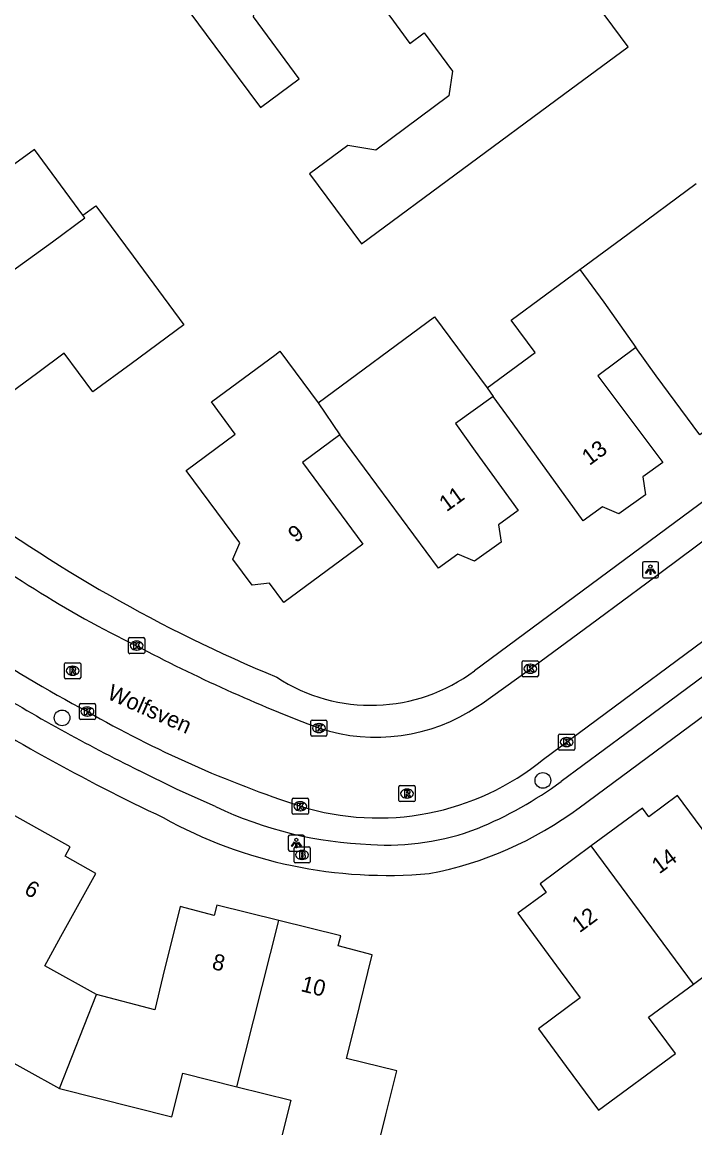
# Model space of a CAD drawing. Extents: x 163427 to 164190, y 380331 to 381641.
# Drawn here: x 163788.9 to 163830.8, y 381101.7 to 381170.4 of the extents above; entities that cross this region are included whole.
import ezdxf

# ---------------------------------------------------------------- set-up
doc = ezdxf.new("R2010")
doc.units = 0
for name, color, linetype in [('IMGEO_Boom', 7, 'Continuous'), ('IMGEO_Brandkraan', 7, 'Continuous'), ('IMGEO_Kolk', 7, 'Continuous'), ('IMGEO_Lichtpunt', 7, 'Continuous'), ('IMGEO_Openbare_ruimte_label', 7, 'Continuous'), ('IMGEO_Pand', 7, 'Continuous'), ('IMGEO_Pand_nummerreeks', 7, 'Continuous'), ('IMGEO_Rijbaan_lokaal_open', 7, 'Continuous'), ('IMGEO_Rioolput', 7, 'Continuous'), ('IMGEO_Voetpad_open', 7, 'Continuous')]:
    doc.layers.add(name, color=color, linetype=linetype)

msp = doc.modelspace()

# ---------------------------------------------------------------- linework, layer by layer
at = {"layer": 'IMGEO_Boom'}
for centre in [(163791.427, 381127.162), (163821.325, 381123.271)]:
    msp.add_circle(centre, 0.489, dxfattribs=at)
at = {"layer": 'IMGEO_Brandkraan'}
for p, q in [((163805.85, 381118.213), (163805.85, 381119.065)), ((163805.925, 381119.139), (163806.777, 381119.139)), ((163806.338, 381118.919), (163806.363, 381118.919)), ((163806.851, 381119.065), (163806.851, 381118.213)), ((163806.361, 381118.359), (163806.336, 381118.359)), ((163806.777, 381118.139), (163805.925, 381118.139))]:
    msp.add_line(p, q, dxfattribs=at)
for points in [[(163805.85, 381118.213), (163805.85, 381119.065)], [(163805.925, 381119.139), (163806.777, 381119.139)], [(163806.851, 381119.065), (163806.851, 381118.213)], [(163806.198, 381118.839), (163806.198, 381118.439), (163806.411, 381118.439)], [(163806.429, 381118.839), (163806.198, 381118.839)], [(163806.377, 381118.758), (163806.323, 381118.758), (163806.323, 381118.682)], [(163806.323, 381118.682), (163806.376, 381118.682)], [(163806.385, 381118.606), (163806.323, 381118.606), (163806.323, 381118.525)], [(163806.323, 381118.525), (163806.385, 381118.525)], [(163806.777, 381118.139), (163805.925, 381118.139)]]:
    msp.add_lwpolyline(points, dxfattribs=at)
for centre, radius, start, end in [((163805.927, 381119.063), 0.0765, 91.55205, 178.44795), ((163805.927, 381119.063), 0.0765, 91.55205, 178.44795), ((163806.775, 381119.063), 0.0765, 1.55205, 88.44795), ((163806.775, 381119.063), 0.0765, 1.55205, 88.44795), ((163805.927, 381118.215), 0.0765, 181.55205, 268.44795), ((163805.927, 381118.215), 0.0765, 181.55205, 268.44795), ((163806.378, 381118.72), 0.0379, 267.82845, 90.93552), ((163806.386, 381118.565), 0.0404, 269.87594, 90.50774), ((163806.417, 381118.69), 0.251, 268.66757, 293.53466), ((163806.433, 381118.694), 0.145, 59.4692, 91.53667), ((163806.458, 381118.741), 0.0922, 285.51372, 58.15012), ((163806.463, 381118.549), 0.105, 301.31148, 78.98903), ((163806.775, 381118.215), 0.0765, 271.55205, 358.44795), ((163806.775, 381118.215), 0.0765, 271.55205, 358.44795)]:
    msp.add_arc(centre, radius, start, end, dxfattribs=at)
for centre, major_axis, ratio, start_param, end_param in [((163806.337, 381118.639), (-0.387, 0.002), 0.722429, 4.712389, 7.853982), ((163806.362, 381118.639), (-0.39, 0.002), 0.717154, 1.570796, 4.712389)]:
    msp.add_ellipse(centre, major_axis=major_axis, ratio=ratio, start_param=start_param, end_param=end_param, dxfattribs=at)
at = {"layer": 'IMGEO_Kolk'}
for p, q in [((163795.563, 381131.229), (163795.563, 381132.081)), ((163795.638, 381132.155), (163796.49, 381132.155)), ((163796.051, 381131.935), (163796.076, 381131.935)), ((163796.564, 381132.081), (163796.564, 381131.229)), ((163796.074, 381131.375), (163796.049, 381131.375)), ((163796.49, 381131.155), (163795.638, 381131.155)), ((163820.041, 381129.792), (163820.041, 381130.644)), ((163820.116, 381130.718), (163820.968, 381130.718)), ((163821.042, 381130.644), (163821.042, 381129.792)), ((163820.552, 381129.938), (163820.527, 381129.938)), ((163820.529, 381130.498), (163820.554, 381130.498)), ((163820.968, 381129.718), (163820.116, 381129.718)), ((163792.504, 381127.129), (163792.504, 381127.981)), ((163792.579, 381128.055), (163793.431, 381128.055)), ((163792.992, 381127.835), (163793.017, 381127.835)), ((163793.505, 381127.981), (163793.505, 381127.129)), ((163793.015, 381127.275), (163792.99, 381127.275)), ((163793.431, 381127.055), (163792.579, 381127.055)), ((163806.897, 381126.103), (163806.897, 381126.955)), ((163806.972, 381127.029), (163807.824, 381127.029)), ((163807.385, 381126.809), (163807.41, 381126.809)), ((163807.898, 381126.955), (163807.898, 381126.103)), ((163807.824, 381126.029), (163806.972, 381126.029)), ((163807.408, 381126.249), (163807.383, 381126.249)), ((163822.303, 381125.232), (163822.303, 381126.084)), ((163822.378, 381126.158), (163823.23, 381126.158)), ((163822.791, 381125.938), (163822.816, 381125.938)), ((163823.304, 381126.084), (163823.304, 381125.232)), ((163823.23, 381125.158), (163822.378, 381125.158)), ((163822.814, 381125.378), (163822.789, 381125.378)), ((163805.741, 381121.241), (163805.741, 381122.093)), ((163805.816, 381122.167), (163806.668, 381122.167)), ((163806.229, 381121.947), (163806.254, 381121.947)), ((163806.742, 381122.093), (163806.742, 381121.241)), ((163806.668, 381121.167), (163805.816, 381121.167)), ((163806.252, 381121.387), (163806.227, 381121.387))]:
    msp.add_line(p, q, dxfattribs=at)
for points in [[(163795.563, 381131.229), (163795.563, 381132.081)], [(163795.638, 381132.155), (163796.49, 381132.155)], [(163796.564, 381132.081), (163796.564, 381131.229)], [(163795.884, 381131.855), (163796.007, 381131.855), (163796.007, 381131.704), (163796.137, 381131.855), (163796.301, 381131.855), (163796.155, 381131.704), (163796.308, 381131.455), (163796.156, 381131.455), (163796.071, 381131.619), (163796.007, 381131.552), (163796.007, 381131.455), (163795.884, 381131.455), (163795.884, 381131.855)], [(163796.49, 381131.155), (163795.638, 381131.155)], [(163820.041, 381129.792), (163820.041, 381130.644)], [(163820.116, 381130.718), (163820.968, 381130.718)], [(163821.042, 381130.644), (163821.042, 381129.792)], [(163820.362, 381130.418), (163820.485, 381130.418), (163820.485, 381130.267), (163820.615, 381130.418), (163820.779, 381130.418), (163820.633, 381130.267), (163820.786, 381130.018), (163820.634, 381130.018), (163820.549, 381130.182), (163820.485, 381130.115), (163820.485, 381130.018), (163820.362, 381130.018), (163820.362, 381130.418)], [(163820.968, 381129.718), (163820.116, 381129.718)], [(163792.504, 381127.129), (163792.504, 381127.981)], [(163792.579, 381128.055), (163793.431, 381128.055)], [(163793.505, 381127.981), (163793.505, 381127.129)], [(163792.825, 381127.755), (163792.948, 381127.755), (163792.948, 381127.604), (163793.078, 381127.755), (163793.242, 381127.755), (163793.096, 381127.604), (163793.249, 381127.355), (163793.097, 381127.355), (163793.012, 381127.519), (163792.948, 381127.452), (163792.948, 381127.355), (163792.825, 381127.355), (163792.825, 381127.755)], [(163793.431, 381127.055), (163792.579, 381127.055)], [(163806.897, 381126.103), (163806.897, 381126.955)], [(163806.972, 381127.029), (163807.824, 381127.029)], [(163807.218, 381126.729), (163807.341, 381126.729), (163807.341, 381126.578), (163807.471, 381126.729), (163807.635, 381126.729), (163807.489, 381126.578), (163807.642, 381126.329), (163807.49, 381126.329), (163807.405, 381126.493), (163807.341, 381126.426), (163807.341, 381126.329), (163807.218, 381126.329), (163807.218, 381126.729)], [(163807.898, 381126.955), (163807.898, 381126.103)], [(163807.824, 381126.029), (163806.972, 381126.029)], [(163822.303, 381125.232), (163822.303, 381126.084)], [(163822.378, 381126.158), (163823.23, 381126.158)], [(163822.624, 381125.858), (163822.747, 381125.858), (163822.747, 381125.707), (163822.877, 381125.858), (163823.041, 381125.858), (163822.895, 381125.707), (163823.048, 381125.458), (163822.896, 381125.458), (163822.811, 381125.622), (163822.747, 381125.555), (163822.747, 381125.458), (163822.624, 381125.458), (163822.624, 381125.858)], [(163823.304, 381126.084), (163823.304, 381125.232)], [(163823.23, 381125.158), (163822.378, 381125.158)], [(163805.741, 381121.241), (163805.741, 381122.093)], [(163805.816, 381122.167), (163806.668, 381122.167)], [(163806.062, 381121.867), (163806.185, 381121.867), (163806.185, 381121.716), (163806.315, 381121.867), (163806.479, 381121.867), (163806.333, 381121.716), (163806.486, 381121.467), (163806.334, 381121.467), (163806.249, 381121.631), (163806.185, 381121.564), (163806.185, 381121.467), (163806.062, 381121.467), (163806.062, 381121.867)], [(163806.742, 381122.093), (163806.742, 381121.241)], [(163806.668, 381121.167), (163805.816, 381121.167)]]:
    msp.add_lwpolyline(points, dxfattribs=at)
for centre, start, end in [((163795.64, 381132.079), 91.55205, 178.44795), ((163795.64, 381132.079), 91.55205, 178.44795), ((163796.488, 381132.079), 1.55205, 88.44795), ((163796.488, 381132.079), 1.55205, 88.44795), ((163795.64, 381131.231), 181.55205, 268.44795), ((163795.64, 381131.231), 181.55205, 268.44795), ((163796.488, 381131.231), 271.55205, 358.44795), ((163796.488, 381131.231), 271.55205, 358.44795), ((163820.118, 381130.642), 91.55205, 178.44795), ((163820.118, 381130.642), 91.55205, 178.44795), ((163820.966, 381130.642), 1.55205, 88.44795), ((163820.966, 381130.642), 1.55205, 88.44795), ((163820.118, 381129.794), 181.55205, 268.44795), ((163820.118, 381129.794), 181.55205, 268.44795), ((163820.966, 381129.794), 271.55205, 358.44795), ((163820.966, 381129.794), 271.55205, 358.44795), ((163792.581, 381127.979), 91.55205, 178.44795), ((163792.581, 381127.979), 91.55205, 178.44795), ((163793.429, 381127.979), 1.55205, 88.44795), ((163793.429, 381127.979), 1.55205, 88.44795), ((163792.581, 381127.131), 181.55205, 268.44795), ((163792.581, 381127.131), 181.55205, 268.44795), ((163793.429, 381127.131), 271.55205, 358.44795), ((163793.429, 381127.131), 271.55205, 358.44795), ((163806.974, 381126.953), 91.55205, 178.44795), ((163806.974, 381126.953), 91.55205, 178.44795), ((163807.822, 381126.953), 1.55205, 88.44795), ((163807.822, 381126.953), 1.55205, 88.44795), ((163806.974, 381126.105), 181.55205, 268.44795), ((163806.974, 381126.105), 181.55205, 268.44795), ((163807.822, 381126.105), 271.55205, 358.44795), ((163807.822, 381126.105), 271.55205, 358.44795), ((163822.38, 381126.082), 91.55205, 178.44795), ((163822.38, 381126.082), 91.55205, 178.44795), ((163823.228, 381126.082), 1.55205, 88.44795), ((163823.228, 381126.082), 1.55205, 88.44795), ((163822.38, 381125.234), 181.55205, 268.44795), ((163822.38, 381125.234), 181.55205, 268.44795), ((163823.228, 381125.234), 271.55205, 358.44795), ((163823.228, 381125.234), 271.55205, 358.44795), ((163805.818, 381122.091), 91.55205, 178.44795), ((163805.818, 381122.091), 91.55205, 178.44795), ((163806.666, 381122.091), 1.55205, 88.44795), ((163806.666, 381122.091), 1.55205, 88.44795), ((163805.818, 381121.243), 181.55205, 268.44795), ((163805.818, 381121.243), 181.55205, 268.44795), ((163806.666, 381121.243), 271.55205, 358.44795), ((163806.666, 381121.243), 271.55205, 358.44795)]:
    msp.add_arc(centre, 0.0765, start, end, dxfattribs=at)
for centre, major_axis, ratio, start_param, end_param in [((163796.05, 381131.655), (-0.387, 0.002), 0.722429, 4.712389, 7.853982), ((163796.075, 381131.655), (-0.39, 0.002), 0.717154, 1.570796, 4.712389), ((163820.528, 381130.218), (-0.387, 0.002), 0.722429, 4.712389, 7.853982), ((163820.553, 381130.218), (-0.39, 0.002), 0.717154, 1.570796, 4.712389), ((163792.991, 381127.555), (-0.387, 0.002), 0.722429, 4.712389, 7.853982), ((163793.016, 381127.555), (-0.39, 0.002), 0.717154, 1.570796, 4.712389), ((163807.384, 381126.529), (-0.387, 0.002), 0.722429, 4.712389, 7.853982), ((163807.409, 381126.529), (-0.39, 0.002), 0.717154, 1.570796, 4.712389), ((163822.79, 381125.658), (-0.387, 0.002), 0.722429, 4.712389, 7.853982), ((163822.815, 381125.658), (-0.39, 0.002), 0.717154, 1.570796, 4.712389), ((163806.228, 381121.667), (-0.387, 0.002), 0.722429, 4.712389, 7.853982), ((163806.253, 381121.667), (-0.39, 0.002), 0.717154, 1.570796, 4.712389)]:
    msp.add_ellipse(centre, major_axis=major_axis, ratio=ratio, start_param=start_param, end_param=end_param, dxfattribs=at)
at = {"layer": 'IMGEO_Lichtpunt'}
for p, q in [((163827.514, 381136.775), (163827.514, 381135.968)), ((163827.514, 381136.775), (163827.514, 381135.968)), ((163828.416, 381136.87), (163827.608, 381136.87)), ((163828.416, 381136.87), (163827.608, 381136.87)), ((163828.51, 381135.968), (163828.51, 381136.775)), ((163828.51, 381135.968), (163828.51, 381136.775)), ((163827.608, 381135.874), (163828.416, 381135.874)), ((163827.608, 381135.874), (163828.416, 381135.874)), ((163805.496, 381119.779), (163805.496, 381118.972)), ((163805.496, 381119.779), (163805.496, 381118.972)), ((163806.398, 381119.874), (163805.59, 381119.874)), ((163806.398, 381119.874), (163805.59, 381119.874)), ((163806.492, 381118.972), (163806.492, 381119.779)), ((163806.492, 381118.972), (163806.492, 381119.779)), ((163805.59, 381118.878), (163806.398, 381118.878)), ((163805.59, 381118.878), (163806.398, 381118.878))]:
    msp.add_line(p, q, dxfattribs=at)
for points in [[(163827.888, 381136.439), (163827.927, 381136.411), (163827.739, 381136.149), (163827.701, 381136.176), (163827.888, 381136.439)], [(163827.99, 381136.391), (163828.037, 381136.391), (163828.037, 381136.069), (163827.99, 381136.069), (163827.99, 381136.391)], [(163828.1, 381136.411), (163828.138, 381136.438), (163828.325, 381136.176), (163828.286, 381136.148), (163828.1, 381136.411)], [(163805.87, 381119.443), (163805.909, 381119.415), (163805.721, 381119.153), (163805.683, 381119.18), (163805.87, 381119.443)], [(163805.972, 381119.395), (163806.019, 381119.395), (163806.019, 381119.073), (163805.972, 381119.073), (163805.972, 381119.395)], [(163806.082, 381119.415), (163806.12, 381119.442), (163806.307, 381119.18), (163806.268, 381119.152), (163806.082, 381119.415)]]:
    msp.add_lwpolyline(points, dxfattribs=at)
for centre in [(163828.013, 381136.573), (163805.995, 381119.577)]:
    msp.add_circle(centre, 0.0994, dxfattribs=at)
for centre, start, end in [((163827.608, 381136.775), 90, 180), ((163827.608, 381136.775), 90, 180), ((163828.416, 381136.775), 0, 90), ((163828.416, 381136.775), 0, 90), ((163827.608, 381135.968), 180, 270), ((163827.608, 381135.968), 180, 270), ((163828.416, 381135.968), 270, 0), ((163828.416, 381135.968), 270, 360), ((163805.59, 381119.779), 90, 180), ((163805.59, 381119.779), 90, 180), ((163806.398, 381119.779), 0, 90), ((163806.398, 381119.779), 0, 90), ((163805.59, 381118.972), 180, 270), ((163805.59, 381118.972), 180, 270), ((163806.398, 381118.972), 270, 0), ((163806.398, 381118.972), 270, 360)]:
    msp.add_arc(centre, 0.0946, start, end, dxfattribs=at)
at = {"layer": 'IMGEO_Pand'}
for points in [[(163811.798, 381170.798), (163813.047, 381169.11), (163813.94, 381169.768), (163815.714, 381167.372), (163815.469, 381165.839), (163810.928, 381162.477), (163809.196, 381162.75), (163806.817, 381160.989), (163810.036, 381156.641), (163822.614, 381165.921), (163826.637, 381168.889), (163824.185, 381172.212), (163822.643, 381172.432), (163823.048, 381175.267), (163821.215, 381177.742)], [(163797.815, 381173.15), (163800.933, 381168.938), (163803.761, 381165.12), (163806.172, 381166.906), (163803.32, 381170.757), (163803.557, 381172.436), (163808.098, 381175.797), (163809.64, 381175.577), (163811.441, 381173.144), (163810.549, 381172.486), (163811.798, 381170.798)], [(163792.727, 381158.423), (163789.707, 381162.519), (163788.041, 381161.291), (163785.927, 381164.27)], [(163823.618, 381155.041), (163826.6, 381157.234), (163830.864, 381160.386)], [(163792.727, 381158.423), (163793.533, 381159.015), (163795.851, 381155.871), (163798.995, 381151.607), (163795.715, 381149.189), (163793.332, 381147.432), (163791.559, 381149.838), (163789.916, 381148.627), (163786.194, 381145.883), (163785.311, 381147.083), (163784.214, 381146.971), (163783.026, 381148.586), (163783.458, 381149.599), (163782.575, 381150.799), (163784.666, 381152.32), (163786.196, 381153.423)], [(163786.196, 381153.423), (163790.84, 381156.772), (163792.851, 381158.255), (163792.727, 381158.423)], [(163834.32, 381155.544), (163831.966, 381153.781), (163833.267, 381152.044), (163835.998, 381148.397), (163834.805, 381147.516), (163834.971, 381146.4), (163833.31, 381145.223), (163832.291, 381145.658), (163831.091, 381144.772), (163828.366, 381148.43), (163827.112, 381150.199)], [(163817.864, 381147.677), (163820.841, 381149.877), (163819.354, 381151.889), (163823.618, 381155.041)], [(163823.618, 381155.041), (163825.11, 381153.022), (163827.112, 381150.199)], [(163807.353, 381146.748), (163814.593, 381152.101), (163817.864, 381147.677)], [(163808.708, 381144.764), (163806.375, 381143.039), (163810.128, 381137.963), (163805.221, 381134.335), (163804.334, 381135.534), (163803.239, 381135.422), (163802.051, 381137.037), (163802.48, 381138.042), (163799.148, 381142.548), (163802.197, 381144.803), (163800.71, 381146.814), (163804.731, 381149.787), (163804.974, 381149.966), (163807.353, 381146.748)], [(163827.112, 381150.199), (163824.75, 381148.44), (163826.045, 381146.701), (163828.772, 381143.04), (163827.539, 381142.153), (163827.706, 381141.032), (163826.045, 381139.855), (163825.025, 381140.29), (163823.826, 381139.407), (163819.474, 381145.443), (163818.239, 381147.156)], [(163818.239, 381147.156), (163815.888, 381145.462), (163817.123, 381143.748), (163819.788, 381140.05), (163818.564, 381139.167), (163818.724, 381138.092), (163817.063, 381136.915), (163816.044, 381137.35), (163814.834, 381136.478), (163808.708, 381144.764)], [(163817.864, 381147.677), (163818.239, 381147.156)], [(163807.353, 381146.748), (163808.708, 381144.764)], [(163830.686, 381110.606), (163833.474, 381112.667), (163835.137, 381110.417), (163842.369, 381115.763), (163840.369, 381118.468), (163838.652, 381120.79), (163833.595, 381117.047), (163832.339, 381118.744), (163829.688, 381122.325), (163827.911, 381121.018), (163827.519, 381121.551), (163824.334, 381119.194)], [(163793.575, 381109.96), (163790.349, 381111.744), (163791.356, 381113.566), (163793.527, 381117.492), (163791.611, 381118.565), (163791.933, 381119.14), (163788.482, 381121.061)], [(163824.334, 381119.194), (163821.148, 381116.836), (163821.537, 381116.304), (163819.765, 381115.007), (163822.404, 381111.428), (163823.646, 381109.743), (163821.044, 381107.824), (163822.772, 381105.488), (163824.787, 381102.765), (163829.56, 381106.294), (163827.897, 381108.544), (163830.686, 381110.606)], [(163830.686, 381110.606), (163824.334, 381119.194)], [(163804.907, 381114.568), (163801.053, 381115.52), (163800.89, 381114.881), (163798.761, 381115.426), (163797.698, 381111.091), (163797.188, 381109.011), (163793.575, 381109.96)], [(163802.299, 381104.224), (163804.907, 381114.568)], [(163802.299, 381104.224), (163805.657, 381103.379), (163804.976, 381100.669), (163810.744, 381099.218), (163811.562, 381102.482), (163812.245, 381105.207), (163809.113, 381105.987), (163809.643, 381108.113), (163810.719, 381112.431), (163808.597, 381112.979), (163808.761, 381113.616), (163804.907, 381114.568)], [(163783.308, 381111.731), (163786.327, 381110.035), (163784.958, 381107.599), (163791.258, 381104.106)], [(163791.258, 381104.106), (163793.575, 381109.96)], [(163791.258, 381104.106), (163798.26, 381102.358), (163798.941, 381105.068), (163802.299, 381104.224)]]:
    msp.add_lwpolyline(points, dxfattribs=at)
at = {"layer": 'IMGEO_Rijbaan_lokaal_open'}
for points in [[(163817.273, 381127.884), (163817.542, 381128.064), (163820.353, 381130.058), (163824.765, 381133.325), (163827.782, 381135.558), (163831.765, 381138.517), (163834.798, 381140.754), (163839.016, 381143.895), (163842.011, 381146.132), (163844.038, 381147.622), (163846.202, 381149.193), (163847.997, 381150.571), (163848.636, 381150.995), (163849.266, 381151.389)], [(163821.372, 381124.599), (163849.013, 381145.068)]]:
    msp.add_lwpolyline(points, dxfattribs=at)
for centre, radius, start, end in [((163825.779, 381192.582), 67.797, 231.71755, 243.9901), ((163838.764, 381213.359), 97.242, 231.84157, 241.92891), ((163841.803, 381217.978), 97.702, 242.07515, 249.40156), ((163810.959, 381137.266), 11.309, 251.81695, 303.93931), ((163828.367, 381189.232), 71.094, 240.17187, 251.86782), ((163811.076, 381137.232), 16.297, 252.74599, 309.18121)]:
    msp.add_arc(centre, radius, start, end, dxfattribs=at)
at = {"layer": 'IMGEO_Rioolput'}
for p, q in [((163791.658, 381130.593), (163792.51, 381130.593)), ((163791.583, 381129.667), (163791.583, 381130.519)), ((163792.071, 381130.373), (163792.096, 381130.373)), ((163792.584, 381130.519), (163792.584, 381129.667)), ((163792.51, 381129.593), (163791.658, 381129.593)), ((163792.094, 381129.813), (163792.069, 381129.813)), ((163812.374, 381122.026), (163812.374, 381122.878)), ((163812.449, 381122.952), (163813.301, 381122.952)), ((163812.862, 381122.732), (163812.887, 381122.732)), ((163813.375, 381122.878), (163813.375, 381122.026)), ((163813.301, 381121.952), (163812.449, 381121.952)), ((163812.885, 381122.172), (163812.86, 381122.172))]:
    msp.add_line(p, q, dxfattribs=at)
for points in [[(163791.658, 381130.593), (163792.51, 381130.593)], [(163791.583, 381129.667), (163791.583, 381130.519)], [(163792.172, 381130.291), (163791.92, 381130.293), (163791.92, 381129.893)], [(163791.92, 381129.893), (163792.044, 381129.893), (163792.044, 381130.055), (163792.055, 381130.055)], [(163792.098, 381130.212), (163792.044, 381130.212), (163792.044, 381130.131)], [(163792.044, 381130.131), (163792.096, 381130.131)], [(163792.102, 381130.026), (163792.173, 381129.893), (163792.313, 381129.893), (163792.248, 381130.019)], [(163792.584, 381130.519), (163792.584, 381129.667)], [(163792.51, 381129.593), (163791.658, 381129.593)], [(163812.374, 381122.026), (163812.374, 381122.878)], [(163812.449, 381122.952), (163813.301, 381122.952)], [(163812.963, 381122.65), (163812.711, 381122.652), (163812.711, 381122.252)], [(163812.711, 381122.252), (163812.835, 381122.252), (163812.835, 381122.414), (163812.846, 381122.414)], [(163812.889, 381122.571), (163812.835, 381122.571), (163812.835, 381122.49)], [(163812.835, 381122.49), (163812.887, 381122.49)], [(163812.893, 381122.385), (163812.964, 381122.252), (163813.104, 381122.252), (163813.039, 381122.378)], [(163813.375, 381122.878), (163813.375, 381122.026)], [(163813.301, 381121.952), (163812.449, 381121.952)]]:
    msp.add_lwpolyline(points, dxfattribs=at)
for centre, radius, start, end in [((163791.66, 381130.517), 0.0765, 91.55205, 178.44795), ((163791.66, 381130.517), 0.0765, 91.55205, 178.44795), ((163792.508, 381130.517), 0.0765, 1.55205, 88.44795), ((163792.508, 381130.517), 0.0765, 1.55205, 88.44795), ((163792.054, 381130.002), 0.0533, 26.02933, 88.69889), ((163792.08, 381130.32), 0.19, 274.7715, 282.96867), ((163792.104, 381130.116), 0.0964, 77.00612, 93.18647), ((163792.118, 381130.173), 0.0378, 276.66336, 79.67722), ((163792.171, 381130.181), 0.109, 350.36119, 89.41601), ((163792.169, 381130.181), 0.112, 277.58423, 350.98172), ((163792.153, 381129.966), 0.108, 29.51342, 73.79051), ((163791.66, 381129.669), 0.0765, 181.55205, 268.44795), ((163791.66, 381129.669), 0.0765, 181.55205, 268.44795), ((163792.508, 381129.669), 0.0765, 271.55205, 358.44795), ((163792.508, 381129.669), 0.0765, 271.55205, 358.44795), ((163812.451, 381122.876), 0.0765, 91.55205, 178.44795), ((163812.451, 381122.876), 0.0765, 91.55205, 178.44795), ((163812.845, 381122.361), 0.0533, 26.02933, 88.69889), ((163812.871, 381122.679), 0.19, 274.7715, 282.96867), ((163812.895, 381122.475), 0.0964, 77.00612, 93.18647), ((163812.909, 381122.532), 0.0378, 276.66336, 79.67722), ((163812.962, 381122.54), 0.109, 350.36119, 89.41601), ((163812.96, 381122.54), 0.112, 277.58423, 350.98172), ((163812.944, 381122.325), 0.108, 29.51342, 73.79051), ((163813.299, 381122.876), 0.0765, 1.55205, 88.44795), ((163813.299, 381122.876), 0.0765, 1.55205, 88.44795), ((163812.451, 381122.028), 0.0765, 181.55205, 268.44795), ((163812.451, 381122.028), 0.0765, 181.55205, 268.44795), ((163813.299, 381122.028), 0.0765, 271.55205, 358.44795), ((163813.299, 381122.028), 0.0765, 271.55205, 358.44795)]:
    msp.add_arc(centre, radius, start, end, dxfattribs=at)
for centre, major_axis, ratio, start_param, end_param in [((163792.07, 381130.093), (-0.387, 0.002), 0.722429, 4.712389, 7.853982), ((163792.095, 381130.093), (-0.39, 0.002), 0.717154, 1.570796, 4.712389), ((163812.861, 381122.452), (-0.387, 0.002), 0.722429, 4.712389, 7.853982), ((163812.886, 381122.452), (-0.39, 0.002), 0.717154, 1.570796, 4.712389)]:
    msp.add_ellipse(centre, major_axis=major_axis, ratio=ratio, start_param=start_param, end_param=end_param, dxfattribs=at)
at = {"layer": 'IMGEO_Voetpad_open'}
for points in [[(163847.678, 381152.747), (163817.071, 381130.093)], [(163823.576, 381121.569), (163851.582, 381142.287)], [(163848.046, 381142.11), (163831.943, 381130.215), (163826.494, 381126.195), (163822.465, 381123.214)], [(163800.972, 381121.65), (163798.589, 381122.714), (163796.208, 381123.885)]]:
    msp.add_lwpolyline(points, dxfattribs=at)
for centre, radius, start, end in [((163840.706, 381216.197), 93.669, 233.26319, 247.44192), ((163810.638, 381138.638), 10.696, 236.74433, 306.97221), ((163850.759, 381233.827), 122.732, 238.47348, 243.61056), ((163850.773, 381233.409), 124.335, 237.116, 244.73978), ((163808.131, 381142.583), 24.096, 292.2378, 306.50378), ((163811.481, 381143.742), 24.465, 244.55981, 267.97786), ((163811.628, 381146.059), 28.695, 240.99562, 275.25988), ((163810.061, 381139.733), 22.64, 280.68675, 306.65263), ((163811.715, 381134.709), 15.455, 265.92833, 290.98446)]:
    msp.add_arc(centre, radius, start, end, dxfattribs=at)

# ---------------------------------------------------------------- texts
at = {"layer": 'IMGEO_Openbare_ruimte_label'}
msp.add_text('Wolfsven', height=1, rotation=336.10152, dxfattribs=at).set_placement((163794.163, 381128.376))
at = {"layer": 'IMGEO_Pand_nummerreeks'}
for s, rotation, p in [('13', 36.29688, (163824.214, 381142.82)), ('11', 35.79267, (163815.333, 381139.944)), ('9', 36.47744, (163805.954, 381138.011)), ('14', 36.40574, (163828.562, 381117.42)), ('6', 330.89374, (163789.002, 381116.257)), ('12', 36.40574, (163823.598, 381113.759)), ('8', 345.93962, (163800.691, 381111.561)), ('10', 345.93962, (163806.222, 381110.176))]:
    msp.add_text(s, height=1, rotation=rotation, dxfattribs=at).set_placement(p)

doc.saveas('drawing.dxf')
